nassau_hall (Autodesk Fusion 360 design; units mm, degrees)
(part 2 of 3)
sketch "Sketch47" plane through (0, 19.3945, 0) normal (0, 1, 0) x axis (-1, 0, 0)
  line L1 (-128, 3) -> (-132.5, 3)
  line L2 (-128, -6) -> (-128, 3)
  line L3 (-132.5, -6) -> (-128, -6)
  line L4 (-132.5, 3) -> (-132.5, -6)
  line L5 (-38, 3) -> (-42.5323, 3)
  line L6 (-38, -6.0191) -> (-38, 3)
  line L7 (-42.5323, -6.0191) -> (-38, -6.0191)
  line L8 (-42.5323, 3) -> (-42.5323, -6.0191)
  line L9 (-128, 26) -> (-132.5, 26)
  line L10 (-128, 17) -> (-128, 26)
  line L11 (-132.5, 17) -> (-128, 17)
  line L12 (-132.5, 26) -> (-132.5, 17)
  line L13 (-53, 3) -> (-57.5, 3)
  line L14 (-53, -6) -> (-53, 3)
  line L15 (-57.5, -6) -> (-53, -6)
  line L16 (-57.5, 3) -> (-57.5, -6)
  line L17 (-98, 3) -> (-102.5, 3)
  line L18 (-98, -6) -> (-98, 3)
  line L19 (-102.5, -6) -> (-98, -6)
  line L20 (-102.5, 3) -> (-102.5, -6)
  line L21 (-83, 26) -> (-87.5, 26)
  line L22 (-83, 17) -> (-83, 26)
  line L23 (-87.5, 17) -> (-83, 17)
  line L24 (-87.5, 26) -> (-87.5, 17)
  line L25 (-38, 45) -> (-42.5, 45)
  line L26 (-38, 38) -> (-38, 45)
  line L27 (-42.5, 38) -> (-38, 38)
  line L28 (-42.5, 45) -> (-42.5, 38)
  line L29 (-98, 45) -> (-102.5, 45)
  line L30 (-98, 38) -> (-98, 45)
  line L31 (-102.5, 38) -> (-98, 38)
  line L32 (-102.5, 45) -> (-102.5, 38)
  line L33 (-143, 45) -> (-147.5, 45)
  line L34 (-143, 38) -> (-143, 45)
  line L35 (-147.5, 38) -> (-143, 38)
  line L36 (-147.5, 45) -> (-147.5, 38)
  line L37 (-83, 45) -> (-87.5, 45)
  line L38 (-83, 38) -> (-83, 45)
  line L39 (-87.5, 38) -> (-83, 38)
  line L40 (-87.5, 45) -> (-87.5, 38)
  line L41 (-38, 26) -> (-42.5, 26)
  line L42 (-38, 17) -> (-38, 26)
  line L43 (-42.5, 17) -> (-38, 17)
  line L44 (-42.5, 26) -> (-42.5, 17)
  line L45 (-98, 26) -> (-102.5, 26)
  line L46 (-98, 17) -> (-98, 26)
  line L47 (-102.5, 17) -> (-98, 17)
  line L48 (-102.5, 26) -> (-102.5, 17)
  line L49 (-68, 26) -> (-72.5, 26)
  line L50 (-68, 17) -> (-68, 26)
  line L51 (-72.5, 17) -> (-68, 17)
  line L52 (-72.5, 26) -> (-72.5, 17)
  line L53 (-53, 45) -> (-57.5, 45)
  line L54 (-53, 38) -> (-53, 45)
  line L55 (-57.5, 38) -> (-53, 38)
  line L56 (-57.5, 45) -> (-57.5, 38)
  line L57 (-113, 45) -> (-117.5, 45)
  line L58 (-113, 38) -> (-113, 45)
  line L59 (-117.5, 38) -> (-113, 38)
  line L60 (-117.5, 45) -> (-117.5, 38)
  line L61 (-128, 45) -> (-132.5, 45)
  line L62 (-128, 38) -> (-128, 45)
  line L63 (-132.5, 38) -> (-128, 38)
  line L64 (-132.5, 45) -> (-132.5, 38)
  line L65 (-68, 45) -> (-72.5, 45)
  line L66 (-68, 38) -> (-68, 45)
  line L67 (-72.5, 38) -> (-68, 38)
  line L68 (-72.5, 45) -> (-72.5, 38)
  line L69 (-53, 26) -> (-57.5, 26)
  line L70 (-53, 17) -> (-53, 26)
  line L71 (-57.5, 17) -> (-53, 17)
  line L72 (-57.5, 26) -> (-57.5, 17)
  line L73 (-113, 26) -> (-117.5, 26)
  line L74 (-113, 16.9958) -> (-113, 26)
  line L75 (-117.5, 16.9958) -> (-113, 16.9958)
  line L76 (-117.5, 26) -> (-117.5, 16.9958)
  line L77 (-83, 3) -> (-87.5, 3)
  line L78 (-83, -6) -> (-83, 3)
  line L79 (-87.5, -6) -> (-83, -6)
  line L80 (-87.5, 3) -> (-87.5, -6)
  line L81 (-143, 3) -> (-147.5, 3)
  line L82 (-143, -6) -> (-143, 3)
  line L83 (-147.5, -6) -> (-143, -6)
  line L84 (-147.5, 3) -> (-147.5, -6)
  line L85 (-143, 26) -> (-147.5, 26)
  line L86 (-143, 17) -> (-143, 26)
  line L87 (-147.5, 17) -> (-143, 17)
  line L88 (-147.5, 26) -> (-147.5, 17)
  line L89 (-68, 3) -> (-72.5, 3)
  line L90 (-68, -6) -> (-68, 3)
  line L91 (-72.5, -6) -> (-68, -6)
  line L92 (-72.5, 3) -> (-72.5, -6)
  line L93 (-113, 3) -> (-117.5, 3)
  line L94 (-113, -6) -> (-113, 3)
  line L95 (-117.5, -6) -> (-113, -6)
  line L96 (-117.5, 3) -> (-117.5, -6)
  line L97 (-33.9524, -14.3624) -> (-160.4524, -14.3624)
  line L98 (-33.9524, 57.1376) -> (-33.9524, -14.3624)
  line L99 (-130.4524, 57.1376) -> (-33.9524, 57.1376)
  line L100 (-130.4524, 55.1376) -> (-130.4524, 57.1376)
  line L101 (-160.4524, 55.1376) -> (-130.4524, 55.1376)
  line L102 (-160.4524, -14.3624) -> (-160.4524, 55.1376)
  line L103 (-2, 3) -> (-6, 3)
  line L104 (-2, -6) -> (-2, 3)
  line L105 (-6, -6) -> (-2, -6)
  line L106 (-6, 3) -> (-6, -6)
  horizontal L103
  vertical L104
  horizontal L105
  vertical L106
sketch "Sketch48" plane through (0, -63.1055, 0) normal (0, -1, 0) x axis (1, 0, 0)
  line L1 (-41.0476, -14.3624) -> (-167.5476, -14.3624)
  line L2 (-41.0476, 57.1376) -> (-41.0476, -14.3624)
  line L3 (-137.5476, 57.1376) -> (-41.0476, 57.1376)
  line L4 (-137.5476, 55.1376) -> (-137.5476, 57.1376)
  line L5 (-167.5476, 55.1376) -> (-137.5476, 55.1376)
  line L6 (-167.5476, -14.3624) -> (-167.5476, 55.1376)
sketch "Sketch49" plane through (0, 19.3945, 0) normal (0, 1, 0) x axis (-1, 0, 0)
  line L1 (124.5, 38) -> (124.5, 45)
  line L2 (120, 38) -> (124.5, 38)
  line L3 (120, 45) -> (120, 38)
  line L4 (124.5, 45) -> (120, 45)
  line L5 (64.5, 38) -> (64.5, 45)
  line L6 (60, 38) -> (64.5, 38)
  line L7 (60, 45) -> (60, 38)
  line L8 (64.5, 45) -> (60, 45)
  line L9 (79.5, 38) -> (79.5, 45)
  line L10 (75, 38) -> (79.5, 38)
  line L11 (75, 45) -> (75, 38)
  line L12 (79.5, 45) -> (75, 45)
  line L13 (139.5, 38) -> (139.5, 45)
  line L14 (135, 38) -> (139.5, 38)
  line L15 (135, 45) -> (135, 38)
  line L16 (139.5, 45) -> (135, 45)
  line L17 (109.5, 38) -> (109.5, 45)
  line L18 (105, 38) -> (109.5, 38)
  line L19 (105, 45) -> (105, 38)
  line L20 (109.5, 45) -> (105, 45)
  line L21 (49.5, 38) -> (49.5, 45)
  line L22 (45, 38) -> (49.5, 38)
  line L23 (45, 45) -> (45, 38)
  line L24 (49.5, 45) -> (45, 45)
  line L25 (94.5, 38) -> (94.5, 45)
  line L26 (90, 38) -> (94.5, 38)
  line L27 (90, 45) -> (90, 38)
  line L28 (94.5, 45) -> (90, 45)
  line L29 (154.5, 38) -> (154.5, 45)
  line L30 (150, 38) -> (154.5, 38)
  line L31 (150, 45) -> (150, 38)
  line L32 (154.5, 45) -> (150, 45)
  line L33 (49.5133, -6) -> (49.5133, 3)
  line L34 (45, -6) -> (49.5133, -6)
  line L35 (45, 3) -> (45, -6)
  line L36 (49.5133, 3) -> (45, 3)
  line L37 (154.5, -6) -> (154.5, 3)
  line L38 (150, -6) -> (154.5, -6)
  line L39 (150, 3) -> (150, -6)
  line L40 (154.5, 3) -> (150, 3)
  line L41 (109.5, 17) -> (109.5, 26)
  line L42 (105, 17) -> (109.5, 17)
  line L43 (105, 26) -> (105, 17)
  line L44 (109.5, 26) -> (105, 26)
  line L45 (79.5, -6) -> (79.5, 3)
  line L46 (75, -6) -> (79.5, -6)
  line L47 (75, 3) -> (75, -6)
  line L48 (79.5, 3) -> (75, 3)
  line L49 (64.5, 17) -> (64.5, 26)
  line L50 (60, 17) -> (64.5, 17)
  line L51 (60, 26) -> (60, 17)
  line L52 (64.5, 26) -> (60, 26)
  line L53 (94.5, 17) -> (94.5, 26)
  line L54 (90, 17) -> (94.5, 17)
  line L55 (90, 26) -> (90, 17)
  line L56 (94.5, 26) -> (90, 26)
  line L57 (124.5, 17) -> (124.5, 26)
  line L58 (120, 17) -> (124.5, 17)
  line L59 (120, 26) -> (120, 17)
  line L60 (124.5, 26) -> (120, 26)
  line L61 (124.5, -6) -> (124.5, 3)
  line L62 (120, -6) -> (124.5, -6)
  line L63 (120, 3) -> (120, -6)
  line L64 (124.5, 3) -> (120, 3)
  line L65 (154.5, 17) -> (154.5, 26)
  line L66 (150, 17) -> (154.5, 17)
  line L67 (150, 26) -> (150, 17)
  line L68 (154.5, 26) -> (150, 26)
  line L69 (109.5, -6) -> (109.5, 3)
  line L70 (105, -6) -> (109.5, -6)
  line L71 (105, 3) -> (105, -6)
  line L72 (109.5, 3) -> (105, 3)
  line L73 (79.5, 17) -> (79.5, 26)
  line L74 (75, 17) -> (79.5, 17)
  line L75 (75, 26) -> (75, 17)
  line L76 (79.5, 26) -> (75, 26)
  line L77 (64.5, -6) -> (64.5, 3)
  line L78 (60, -6) -> (64.5, -6)
  line L79 (60, 3) -> (60, -6)
  line L80 (64.5, 3) -> (60, 3)
  line L81 (94.5, -6) -> (94.5, 3)
  line L82 (90, -6) -> (94.5, -6)
  line L83 (90, 3) -> (90, -6)
  line L84 (94.5, 3) -> (90, 3)
  line L85 (139.5, 17) -> (139.5, 26)
  line L86 (135, 17) -> (139.5, 17)
  line L87 (135, 26) -> (135, 17)
  line L88 (139.5, 26) -> (135, 26)
  line L89 (139.5, -6) -> (139.5, 3)
  line L90 (135, -6) -> (139.5, -6)
  line L91 (135, 3) -> (135, -6)
  line L92 (139.5, 3) -> (135, 3)
  line L93 (49.5073, 17) -> (49.5073, 26)
  line L94 (45, 17) -> (49.5073, 17)
  line L95 (45, 26) -> (45, 17)
  line L96 (49.5073, 26) -> (45, 26)
  line L97 (167.5476, -14.3624) -> (41.0476, -14.3624)
  line L98 (167.5476, 55.1376) -> (167.5476, -14.3624)
  line L99 (137.5476, 55.1376) -> (167.5476, 55.1376)
  line L100 (137.5476, 57.1376) -> (137.5476, 55.1376)
  line L101 (41.0476, 57.1376) -> (137.5476, 57.1376)
  line L102 (41.0476, -14.3624) -> (41.0476, 57.1376)
sketch "Sketch50" plane through (0, 19.3945, 0) normal (0, 1, 0) x axis (-1, 0, 0)
extrude "Extrude39" cut sketch "Sketch49" profile of L93 L94 L95 L96 against normal blind 100
extrude "Extrude40" cut sketch "Sketch47" profile of L5 L6 L7 L8 L13 L14 L15 L16 L17 L18 L19 L20 L77 L78 L79 L80 L89 L90 L91 L92 L93 L94 L95 L96 against normal blind 100
sketch "Sketch51" plane through (0, -61.1302, 0) normal (0, 1, 0) x axis (-1, 0, 0)
  line L1 (-33.9524, -14.3624) -> (-157.9638, -14.3624)
  line L2 (-33.9524, 55.6376) -> (-33.9524, -14.3624)
  line L3 (-157.9638, 55.6376) -> (-33.9524, 55.6376)
  line L4 (-157.9638, -14.3624) -> (-157.9638, 55.6376)
  line L5 (-38, -6.0191) -> (-38, 3)
  line L6 (-42.5323, -6.0191) -> (-38, -6.0191)
  line L7 (-42.5323, 3) -> (-42.5323, -6.0191)
  line L8 (-38, 3) -> (-42.5323, 3)
  line L9 (-98, -6) -> (-98, 3)
  line L10 (-102.5, -6) -> (-98, -6)
  line L11 (-102.5, 3) -> (-102.5, -6)
  line L12 (-98, 3) -> (-102.5, 3)
  line L13 (-83, -6) -> (-83, 3)
  line L14 (-87.5, -6) -> (-83, -6)
  line L15 (-87.5, 3) -> (-87.5, -6)
  line L16 (-83, 3) -> (-87.5, 3)
  line L17 (-53, -6) -> (-53, 3)
  line L18 (-57.5, -6) -> (-53, -6)
  line L19 (-57.5, 3) -> (-57.5, -6)
  line L20 (-53, 3) -> (-57.5, 3)
  line L21 (-113, -6) -> (-113, 3)
  line L22 (-117.5, -6) -> (-113, -6)
  line L23 (-117.5, 3) -> (-117.5, -6)
  line L24 (-113, 3) -> (-117.5, 3)
  line L25 (-68, -6) -> (-68, 3)
  line L26 (-72.5, -6) -> (-68, -6)
  line L27 (-72.5, 3) -> (-72.5, -6)
  line L28 (-68, 3) -> (-72.5, 3)
sketch "Sketch52" plane through (0, -61, 0) normal (0, 1, 0) x axis (-1, 0, 0)
  line L1 (45, 17) -> (49.5073, 17)
  line L2 (45, 26) -> (45, 17)
  line L3 (49.5073, 26) -> (45, 26)
  line L4 (49.5073, 17) -> (49.5073, 26)
  line L5 (166, -14.3624) -> (41.0476, -14.3624)
  line L6 (166, 55.6376) -> (166, -14.3624)
  line L7 (41.0476, 55.6376) -> (166, 55.6376)
  line L8 (41.0476, -14.3624) -> (41.0476, 55.6376)
  line L9 (64.5607, 26) -> (60, 26)
  line L10 (64.5607, 16.951) -> (64.5607, 26)
  line L11 (60, 16.951) -> (64.5607, 16.951)
  line L12 (60, 26) -> (60, 16.951)
  horizontal L9
  vertical L10
  horizontal L11
  vertical L12
extrude "Extrude41" cut sketch "Sketch52" profile of L9 L10 L11 L12 against normal blind 100
sketch "Sketch53" plane through (0, 19.3945, 0) normal (0, 1, 0) x axis (-1, 0, 0)
  line L1 (124.5, 38) -> (124.5, 45)
  line L2 (120, 38) -> (124.5, 38)
  line L3 (120, 45) -> (120, 38)
  line L4 (124.5, 45) -> (120, 45)
  line L5 (64.5, 38) -> (64.5, 45)
  line L6 (60, 38) -> (64.5, 38)
  line L7 (60, 45) -> (60, 38)
  line L8 (64.5, 45) -> (60, 45)
  line L9 (79.5, 38) -> (79.5, 45)
  line L10 (75, 38) -> (79.5, 38)
  line L11 (75, 45) -> (75, 38)
  line L12 (79.5, 45) -> (75, 45)
  line L13 (139.5, 38) -> (139.5, 45)
  line L14 (135, 38) -> (139.5, 38)
  line L15 (135, 45) -> (135, 38)
  line L16 (139.5, 45) -> (135, 45)
  line L17 (109.5, 38) -> (109.5, 45)
  line L18 (105, 38) -> (109.5, 38)
  line L19 (105, 45) -> (105, 38)
  line L20 (109.5, 45) -> (105, 45)
  line L21 (49.5, 38) -> (49.5, 45)
  line L22 (45, 38) -> (49.5, 38)
  line L23 (45, 45) -> (45, 38)
  line L24 (49.5, 45) -> (45, 45)
  line L25 (94.5, 38) -> (94.5, 45)
  line L26 (90, 38) -> (94.5, 38)
  line L27 (90, 45) -> (90, 38)
  line L28 (94.5, 45) -> (90, 45)
  line L29 (154.5, 38) -> (154.5, 45)
  line L30 (150, 38) -> (154.5, 38)
  line L31 (150, 45) -> (150, 38)
  line L32 (154.5, 45) -> (150, 45)
  line L33 (49.5133, -6) -> (49.5133, 3)
  line L34 (45, -6) -> (49.5133, -6)
  line L35 (45, 3) -> (45, -6)
  line L36 (49.5133, 3) -> (45, 3)
  line L37 (154.5, -6) -> (154.5, 3)
  line L38 (150, -6) -> (154.5, -6)
  line L39 (150, 3) -> (150, -6)
  line L40 (154.5, 3) -> (150, 3)
  line L41 (109.5, 17) -> (109.5, 26)
  line L42 (105, 17) -> (109.5, 17)
  line L43 (105, 26) -> (105, 17)
  line L44 (109.5, 26) -> (105, 26)
  line L45 (79.5, -6) -> (79.5, 3)
  line L46 (75, -6) -> (79.5, -6)
  line L47 (75, 3) -> (75, -6)
  line L48 (79.5, 3) -> (75, 3)
  line L49 (64.5, 17) -> (64.5, 26)
  line L50 (60, 17) -> (64.5, 17)
  line L51 (60, 26) -> (60, 17)
  line L52 (64.5, 26) -> (60, 26)
  line L53 (94.5, 17) -> (94.5, 26)
  line L54 (90, 17) -> (94.5, 17)
  line L55 (90, 26) -> (90, 17)
  line L56 (94.5, 26) -> (90, 26)
  line L57 (124.5, 17) -> (124.5, 26)
  line L58 (120, 17) -> (124.5, 17)
  line L59 (120, 26) -> (120, 17)
  line L60 (124.5, 26) -> (120, 26)
  line L61 (124.5, -6) -> (124.5, 3)
  line L62 (120, -6) -> (124.5, -6)
  line L63 (120, 3) -> (120, -6)
  line L64 (124.5, 3) -> (120, 3)
  line L65 (154.5, 17) -> (154.5, 26)
  line L66 (150, 17) -> (154.5, 17)
  line L67 (150, 26) -> (150, 17)
  line L68 (154.5, 26) -> (150, 26)
  line L69 (109.5, -6) -> (109.5, 3)
  line L70 (105, -6) -> (109.5, -6)
  line L71 (105, 3) -> (105, -6)
  line L72 (109.5, 3) -> (105, 3)
  line L73 (79.5, 17) -> (79.5, 26)
  line L74 (75, 17) -> (79.5, 17)
  line L75 (75, 26) -> (75, 17)
  line L76 (79.5, 26) -> (75, 26)
  line L77 (64.5, -6) -> (64.5, 3)
  line L78 (60, -6) -> (64.5, -6)
  line L79 (60, 3) -> (60, -6)
  line L80 (64.5, 3) -> (60, 3)
  line L81 (94.5, -6) -> (94.5, 3)
  line L82 (90, -6) -> (94.5, -6)
  line L83 (90, 3) -> (90, -6)
  line L84 (94.5, 3) -> (90, 3)
  line L85 (139.5, 17) -> (139.5, 26)
  line L86 (135, 17) -> (139.5, 17)
  line L87 (135, 26) -> (135, 17)
  line L88 (139.5, 26) -> (135, 26)
  line L89 (139.5, -6) -> (139.5, 3)
  line L90 (135, -6) -> (139.5, -6)
  line L91 (135, 3) -> (135, -6)
  line L92 (139.5, 3) -> (135, 3)
  line L93 (49.5073, 17) -> (49.5073, 26)
  line L94 (45, 17) -> (49.5073, 17)
  line L95 (45, 26) -> (45, 17)
  line L96 (49.5073, 26) -> (45, 26)
  line L97 (167.5476, -14.3624) -> (41.0476, -14.3624)
  line L98 (167.5476, 55.1376) -> (167.5476, -14.3624)
  line L99 (137.5476, 55.1376) -> (167.5476, 55.1376)
  line L100 (137.5476, 57.1376) -> (137.5476, 55.1376)
  line L101 (41.0476, 57.1376) -> (137.5476, 57.1376)
  line L102 (41.0476, -14.3624) -> (41.0476, 57.1376)
extrude "Extrude39" new body sketch "Sketch53" profile of L21 L22 L23 L24 along normal blind 100
extrude "Extrude40" cut of existing geometry blind -200
sketch "Sketch54" plane through (0, -61, 0) normal (0, 1, 0) x axis (-1, 0, 0)
  line L1 (45, 38) -> (49.5, 38)
  line L2 (45, 45) -> (45, 38)
  line L3 (49.5, 45) -> (45, 45)
  line L4 (49.5, 38) -> (49.5, 45)
  line L5 (64.5607, 16.951) -> (64.5607, 26)
  line L6 (60, 16.951) -> (64.5607, 16.951)
  line L7 (60, 26) -> (60, 16.951)
  line L8 (64.5607, 26) -> (60, 26)
  line L9 (45, 17) -> (49.5073, 17)
  line L10 (45, 26) -> (45, 17)
  line L11 (49.5073, 26) -> (45, 26)
  line L12 (49.5073, 17) -> (49.5073, 26)
  line L13 (166, -14.3624) -> (41.0476, -14.3624)
  line L14 (166, 55.6376) -> (166, -14.3624)
  line L15 (41.0476, 55.6376) -> (166, 55.6376)
  line L16 (41.0476, -14.3624) -> (41.0476, 55.6376)
  line L17 (49.4925, 3) -> (45, 3)
  line L18 (49.4925, -5.9059) -> (49.4925, 3)
  line L19 (45, -5.9059) -> (49.4925, -5.9059)
  line L20 (45, 3) -> (45, -5.9059)
  line L21 (64.5, 3) -> (60, 3)
  line L22 (64.5, -6) -> (64.5, 3)
  line L23 (60, -6) -> (64.5, -6)
  line L24 (60, 3) -> (60, -6)
  line L25 (64.5, 45) -> (60, 45)
  line L26 (64.5, 37.9022) -> (64.5, 45)
  line L27 (60, 37.9022) -> (64.5, 37.9022)
  line L28 (60, 45) -> (60, 37.9022)
  horizontal L17
  vertical L18
  horizontal L19
  vertical L20
  horizontal L21
  vertical L22
  horizontal L23
  vertical L24
  horizontal L25
  vertical L26
  horizontal L27
  vertical L28
extrude "Extrude43" cut sketch "Sketch54" profile of L17 L18 L19 L20 L21 L22 L23 L24 L25 L26 L27 L28 against normal blind 100
sketch "Sketch55" plane through (0, 19.3945, 0) normal (0, 1, 0) x axis (-1, 0, 0)
  line L1 (124.5, 38) -> (124.5, 45)
  line L2 (120, 38) -> (124.5, 38)
  line L3 (120, 45) -> (120, 38)
  line L4 (124.5, 45) -> (120, 45)
  line L5 (64.5, 38) -> (64.5, 45)
  line L6 (60, 38) -> (64.5, 38)
  line L7 (60, 45) -> (60, 38)
  line L8 (64.5, 45) -> (60, 45)
  line L9 (79.5, 38) -> (79.5, 45)
  line L10 (75, 38) -> (79.5, 38)
  line L11 (75, 45) -> (75, 38)
  line L12 (79.5, 45) -> (75, 45)
  line L13 (139.5, 38) -> (139.5, 45)
  line L14 (135, 38) -> (139.5, 38)
  line L15 (135, 45) -> (135, 38)
  line L16 (139.5, 45) -> (135, 45)
  line L17 (109.5, 38) -> (109.5, 45)
  line L18 (105, 38) -> (109.5, 38)
  line L19 (105, 45) -> (105, 38)
  line L20 (109.5, 45) -> (105, 45)
  line L21 (49.5, 38) -> (49.5, 45)
  line L22 (45, 38) -> (49.5, 38)
  line L23 (45, 45) -> (45, 38)
  line L24 (49.5, 45) -> (45, 45)
  line L25 (94.5, 38) -> (94.5, 45)
  line L26 (90, 38) -> (94.5, 38)
  line L27 (90, 45) -> (90, 38)
  line L28 (94.5, 45) -> (90, 45)
  line L29 (154.5, 38) -> (154.5, 45)
  line L30 (150, 38) -> (154.5, 38)
  line L31 (150, 45) -> (150, 38)
  line L32 (154.5, 45) -> (150, 45)
  line L33 (49.5133, -6) -> (49.5133, 3)
  line L34 (45, -6) -> (49.5133, -6)
  line L35 (45, 3) -> (45, -6)
  line L36 (49.5133, 3) -> (45, 3)
  line L37 (154.5, -6) -> (154.5, 3)
  line L38 (150, -6) -> (154.5, -6)
  line L39 (150, 3) -> (150, -6)
  line L40 (154.5, 3) -> (150, 3)
  line L41 (109.5, 17) -> (109.5, 26)
  line L42 (105, 17) -> (109.5, 17)
  line L43 (105, 26) -> (105, 17)
  line L44 (109.5, 26) -> (105, 26)
  line L45 (79.5, -6) -> (79.5, 3)
  line L46 (75, -6) -> (79.5, -6)
  line L47 (75, 3) -> (75, -6)
  line L48 (79.5, 3) -> (75, 3)
  line L49 (64.5, 17) -> (64.5, 26)
  line L50 (60, 17) -> (64.5, 17)
  line L51 (60, 26) -> (60, 17)
  line L52 (64.5, 26) -> (60, 26)
  line L53 (94.5, 17) -> (94.5, 26)
  line L54 (90, 17) -> (94.5, 17)
  line L55 (90, 26) -> (90, 17)
  line L56 (94.5, 26) -> (90, 26)
  line L57 (124.5, 17) -> (124.5, 26)
  line L58 (120, 17) -> (124.5, 17)
  line L59 (120, 26) -> (120, 17)
  line L60 (124.5, 26) -> (120, 26)
  line L61 (124.5, -6) -> (124.5, 3)
  line L62 (120, -6) -> (124.5, -6)
  line L63 (120, 3) -> (120, -6)
  line L64 (124.5, 3) -> (120, 3)
  line L65 (154.5, 17) -> (154.5, 26)
  line L66 (150, 17) -> (154.5, 17)
  line L67 (150, 26) -> (150, 17)
  line L68 (154.5, 26) -> (150, 26)
  line L69 (109.5, -6) -> (109.5, 3)
  line L70 (105, -6) -> (109.5, -6)
  line L71 (105, 3) -> (105, -6)
  line L72 (109.5, 3) -> (105, 3)
  line L73 (79.5, 17) -> (79.5, 26)
  line L74 (75, 17) -> (79.5, 17)
  line L75 (75, 26) -> (75, 17)
  line L76 (79.5, 26) -> (75, 26)
  line L77 (64.5, -6) -> (64.5, 3)
  line L78 (60, -6) -> (64.5, -6)
  line L79 (60, 3) -> (60, -6)
  line L80 (64.5, 3) -> (60, 3)
  line L81 (94.5, -6) -> (94.5, 3)
  line L82 (90, -6) -> (94.5, -6)
  line L83 (90, 3) -> (90, -6)
  line L84 (94.5, 3) -> (90, 3)
  line L85 (139.5, 17) -> (139.5, 26)
  line L86 (135, 17) -> (139.5, 17)
  line L87 (135, 26) -> (135, 17)
  line L88 (139.5, 26) -> (135, 26)
  line L89 (139.5, -6) -> (139.5, 3)
  line L90 (135, -6) -> (139.5, -6)
  line L91 (135, 3) -> (135, -6)
  line L92 (139.5, 3) -> (135, 3)
  line L93 (49.5073, 17) -> (49.5073, 26)
  line L94 (45, 17) -> (49.5073, 17)
  line L95 (45, 26) -> (45, 17)
  line L96 (49.5073, 26) -> (45, 26)
  line L97 (167.5476, -14.3624) -> (41.0476, -14.3624)
  line L98 (167.5476, 55.1376) -> (167.5476, -14.3624)
  line L99 (137.5476, 55.1376) -> (167.5476, 55.1376)
  line L100 (137.5476, 57.1376) -> (137.5476, 55.1376)
  line L101 (41.0476, 57.1376) -> (137.5476, 57.1376)
  line L102 (41.0476, -14.3624) -> (41.0476, 57.1376)
  line L103 (79.5, 45) -> (75, 45)
  line L104 (79.5, 38) -> (79.5, 45)
  line L105 (75, 38) -> (79.5, 38)
  line L106 (75, 45) -> (75, 38)
  line L107 (79.5, 26) -> (75, 26)
  line L108 (79.5, 17) -> (79.5, 26)
  line L109 (75, 17) -> (79.5, 17)
  line L110 (75, 26) -> (75, 17)
  line L111 (79.5, 2.7917) -> (75, 2.7917)
  line L112 (79.5, -6) -> (79.5, 2.7917)
  line L113 (75, -6) -> (79.5, -6)
  line L114 (75, 2.7917) -> (75, -6)
  point P11 (79.5, 38)
  point P106 (79.5, 38)
  point P13 (75, 45)
  point P104 (75, 45)
  point P75 (79.5, 17)
  point P110 (79.5, 17)
  point P77 (75, 26)
  point P108 (75, 26)
  point P47 (79.5, -6)
  point P114 (79.5, -6)
  point P112 (75, 2.7917)
  horizontal L103
  vertical L104
  horizontal L105
  vertical L106
  coincident P11 P106
  coincident P13 P104
  horizontal L107
  vertical L108
  horizontal L109
  vertical L110
  coincident P75 P110
  coincident P77 P108
  horizontal L111
  vertical L112
  horizontal L113
  vertical L114
  coincident P47 P114
  coincident L47 P112
extrude "Extrude44" cut sketch "Sketch55" profile of L9 L10 L11 L12 L45 L46 L47 L73 L74 L75 L76 L103 L104 L105 L106 L107 L108 L109 L110 L111 L112 L113 L114 against normal blind 100
sketch "Sketch56" plane through (0, 19.3945, 0) normal (0, 1, 0) x axis (-1, 0, 0)
  line L1 (124.5, 38) -> (124.5, 45)
  line L2 (120, 38) -> (124.5, 38)
  line L3 (120, 45) -> (120, 38)
  line L4 (124.5, 45) -> (120, 45)
  line L5 (64.5, 38) -> (64.5, 45)
  line L6 (60, 38) -> (64.5, 38)
  line L7 (60, 45) -> (60, 38)
  line L8 (64.5, 45) -> (60, 45)
  line L9 (79.5, 38) -> (79.5, 45)
  line L10 (75, 38) -> (79.5, 38)
  line L11 (75, 45) -> (75, 38)
  line L12 (79.5, 45) -> (75, 45)
  line L13 (139.5, 38) -> (139.5, 45)
  line L14 (135, 38) -> (139.5, 38)
  line L15 (135, 45) -> (135, 38)
  line L16 (139.5, 45) -> (135, 45)
  line L17 (109.5, 38) -> (109.5, 45)
  line L18 (105, 38) -> (109.5, 38)
  line L19 (105, 45) -> (105, 38)
  line L20 (109.5, 45) -> (105, 45)
  line L21 (49.5, 38) -> (49.5, 45)
  line L22 (45, 38) -> (49.5, 38)
  line L23 (45, 45) -> (45, 38)
  line L24 (49.5, 45) -> (45, 45)
  line L25 (94.5, 38) -> (94.5, 45)
  line L26 (90, 38) -> (94.5, 38)
  line L27 (90, 45) -> (90, 38)
  line L28 (94.5, 45) -> (90, 45)
  line L29 (154.5, 38) -> (154.5, 45)
  line L30 (150, 38) -> (154.5, 38)
  line L31 (150, 45) -> (150, 38)
  line L32 (154.5, 45) -> (150, 45)
  line L33 (49.5133, -6) -> (49.5133, 3)
  line L34 (45, -6) -> (49.5133, -6)
  line L35 (45, 3) -> (45, -6)
  line L36 (49.5133, 3) -> (45, 3)
  line L37 (154.5, -6) -> (154.5, 3)
  line L38 (150, -6) -> (154.5, -6)
  line L39 (150, 3) -> (150, -6)
  line L40 (154.5, 3) -> (150, 3)
  line L41 (109.5, 17) -> (109.5, 26)
  line L42 (105, 17) -> (109.5, 17)
  line L43 (105, 26) -> (105, 17)
  line L44 (109.5, 26) -> (105, 26)
  line L45 (79.5, -6) -> (79.5, 3)
  line L46 (75, -6) -> (79.5, -6)
  line L47 (75, 3) -> (75, -6)
  line L48 (79.5, 3) -> (75, 3)
  line L49 (64.5, 17) -> (64.5, 26)
  line L50 (60, 17) -> (64.5, 17)
  line L51 (60, 26) -> (60, 17)
  line L52 (64.5, 26) -> (60, 26)
  line L53 (94.5, 17) -> (94.5, 26)
  line L54 (90, 17) -> (94.5, 17)
  line L55 (90, 26) -> (90, 17)
  line L56 (94.5, 26) -> (90, 26)
  line L57 (124.5, 17) -> (124.5, 26)
  line L58 (120, 17) -> (124.5, 17)
  line L59 (120, 26) -> (120, 17)
  line L60 (124.5, 26) -> (120, 26)
  line L61 (124.5, -6) -> (124.5, 3)
  line L62 (120, -6) -> (124.5, -6)
  line L63 (120, 3) -> (120, -6)
  line L64 (124.5, 3) -> (120, 3)
  line L65 (154.5, 17) -> (154.5, 26)
  line L66 (150, 17) -> (154.5, 17)
  line L67 (150, 26) -> (150, 17)
  line L68 (154.5, 26) -> (150, 26)
  line L69 (109.5, -6) -> (109.5, 3)
  line L70 (105, -6) -> (109.5, -6)
  line L71 (105, 3) -> (105, -6)
  line L72 (109.5, 3) -> (105, 3)
  line L73 (79.5, 17) -> (79.5, 26)
  line L74 (75, 17) -> (79.5, 17)
  line L75 (75, 26) -> (75, 17)
  line L76 (79.5, 26) -> (75, 26)
  line L77 (64.5, -6) -> (64.5, 3)
  line L78 (60, -6) -> (64.5, -6)
  line L79 (60, 3) -> (60, -6)
  line L80 (64.5, 3) -> (60, 3)
  line L81 (94.5, -6) -> (94.5, 3)
  line L82 (90, -6) -> (94.5, -6)
  line L83 (90, 3) -> (90, -6)
  line L84 (94.5, 3) -> (90, 3)
  line L85 (139.5, 17) -> (139.5, 26)
  line L86 (135, 17) -> (139.5, 17)
  line L87 (135, 26) -> (135, 17)
  line L88 (139.5, 26) -> (135, 26)
  line L89 (139.5, -6) -> (139.5, 3)
  line L90 (135, -6) -> (139.5, -6)
  line L91 (135, 3) -> (135, -6)
  line L92 (139.5, 3) -> (135, 3)
  line L93 (49.5073, 17) -> (49.5073, 26)
  line L94 (45, 17) -> (49.5073, 17)
  line L95 (45, 26) -> (45, 17)
  line L96 (49.5073, 26) -> (45, 26)
  line L97 (167.5476, -14.3624) -> (41.0476, -14.3624)
  line L98 (167.5476, 55.1376) -> (167.5476, -14.3624)
  line L99 (137.5476, 55.1376) -> (167.5476, 55.1376)
  line L100 (137.5476, 57.1376) -> (137.5476, 55.1376)
  line L101 (41.0476, 57.1376) -> (137.5476, 57.1376)
  line L102 (41.0476, -14.3624) -> (41.0476, 57.1376)
extrude "Extrude45" cut sketch "Sketch56" profile of L1 L2 L3 L4 L13 L14 L15 L16 L17 L18 L19 L20 L25 L26 L27 L28 L29 L30 L31 L32 L37 L38 L39 L40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 against normal blind 100
sketch "Sketch57" plane through (0, 19.3945, 0) normal (0, 1, 0) x axis (-1, 0, 0)
  line L1 (-128, 3) -> (-132.5, 3)
  line L2 (-128, -6) -> (-128, 3)
  line L3 (-132.5, -6) -> (-128, -6)
  line L4 (-132.5, 3) -> (-132.5, -6)
  line L5 (-38, 3) -> (-42.5323, 3)
  line L6 (-38, -6.0191) -> (-38, 3)
  line L7 (-42.5323, -6.0191) -> (-38, -6.0191)
  line L8 (-42.5323, 3) -> (-42.5323, -6.0191)
  line L9 (-128, 26) -> (-132.5, 26)
  line L10 (-128, 17) -> (-128, 26)
  line L11 (-132.5, 17) -> (-128, 17)
  line L12 (-132.5, 26) -> (-132.5, 17)
  line L13 (-53, 3) -> (-57.5, 3)
  line L14 (-53, -6) -> (-53, 3)
  line L15 (-57.5, -6) -> (-53, -6)
  line L16 (-57.5, 3) -> (-57.5, -6)
  line L17 (-98, 3) -> (-102.5, 3)
  line L18 (-98, -6) -> (-98, 3)
  line L19 (-102.5, -6) -> (-98, -6)
  line L20 (-102.5, 3) -> (-102.5, -6)
  line L21 (-83, 26) -> (-87.5, 26)
  line L22 (-83, 17) -> (-83, 26)
  line L23 (-87.5, 17) -> (-83, 17)
  line L24 (-87.5, 26) -> (-87.5, 17)
  line L25 (-38, 45) -> (-42.5, 45)
  line L26 (-38, 38) -> (-38, 45)
  line L27 (-42.5, 38) -> (-38, 38)
  line L28 (-42.5, 45) -> (-42.5, 38)
  line L29 (-98, 45) -> (-102.5, 45)
  line L30 (-98, 38) -> (-98, 45)
  line L31 (-102.5, 38) -> (-98, 38)
  line L32 (-102.5, 45) -> (-102.5, 38)
  line L33 (-143, 45) -> (-147.5, 45)
  line L34 (-143, 38) -> (-143, 45)
  line L35 (-147.5, 38) -> (-143, 38)
  line L36 (-147.5, 45) -> (-147.5, 38)
  line L37 (-83, 45) -> (-87.5, 45)
  line L38 (-83, 38) -> (-83, 45)
  line L39 (-87.5, 38) -> (-83, 38)
  line L40 (-87.5, 45) -> (-87.5, 38)
  line L41 (-38, 26) -> (-42.5, 26)
  line L42 (-38, 17) -> (-38, 26)
  line L43 (-42.5, 17) -> (-38, 17)
  line L44 (-42.5, 26) -> (-42.5, 17)
  line L45 (-98, 26) -> (-102.5, 26)
  line L46 (-98, 17) -> (-98, 26)
  line L47 (-102.5, 17) -> (-98, 17)
  line L48 (-102.5, 26) -> (-102.5, 17)
  line L49 (-68, 26) -> (-72.5, 26)
  line L50 (-68, 17) -> (-68, 26)
  line L51 (-72.5, 17) -> (-68, 17)
  line L52 (-72.5, 26) -> (-72.5, 17)
  line L53 (-53, 45) -> (-57.5, 45)
  line L54 (-53, 38) -> (-53, 45)
  line L55 (-57.5, 38) -> (-53, 38)
  line L56 (-57.5, 45) -> (-57.5, 38)
  line L57 (-113, 45) -> (-117.5, 45)
  line L58 (-113, 38) -> (-113, 45)
  line L59 (-117.5, 38) -> (-113, 38)
  line L60 (-117.5, 45) -> (-117.5, 38)
  line L61 (-128, 45) -> (-132.5, 45)
  line L62 (-128, 38) -> (-128, 45)
  line L63 (-132.5, 38) -> (-128, 38)
  line L64 (-132.5, 45) -> (-132.5, 38)
  line L65 (-68, 45) -> (-72.5, 45)
  line L66 (-68, 38) -> (-68, 45)
  line L67 (-72.5, 38) -> (-68, 38)
  line L68 (-72.5, 45) -> (-72.5, 38)
  line L69 (-53, 26) -> (-57.5, 26)
  line L70 (-53, 17) -> (-53, 26)
  line L71 (-57.5, 17) -> (-53, 17)
  line L72 (-57.5, 26) -> (-57.5, 17)
  line L73 (-113, 26) -> (-117.5, 26)
  line L74 (-113, 16.9958) -> (-113, 26)
  line L75 (-117.5, 16.9958) -> (-113, 16.9958)
  line L76 (-117.5, 26) -> (-117.5, 16.9958)
  line L77 (-83, 3) -> (-87.5, 3)
  line L78 (-83, -6) -> (-83, 3)
  line L79 (-87.5, -6) -> (-83, -6)
  line L80 (-87.5, 3) -> (-87.5, -6)
  line L81 (-143, 3) -> (-147.5, 3)
  line L82 (-143, -6) -> (-143, 3)
  line L83 (-147.5, -6) -> (-143, -6)
  line L84 (-147.5, 3) -> (-147.5, -6)
  line L85 (-143, 26) -> (-147.5, 26)
  line L86 (-143, 17) -> (-143, 26)
  line L87 (-147.5, 17) -> (-143, 17)
  line L88 (-147.5, 26) -> (-147.5, 17)
  line L89 (-68, 3) -> (-72.5, 3)
  line L90 (-68, -6) -> (-68, 3)
  line L91 (-72.5, -6) -> (-68, -6)
  line L92 (-72.5, 3) -> (-72.5, -6)
  line L93 (-113, 3) -> (-117.5, 3)
  line L94 (-113, -6) -> (-113, 3)
  line L95 (-117.5, -6) -> (-113, -6)
  line L96 (-117.5, 3) -> (-117.5, -6)
  line L97 (-33.9524, -14.3624) -> (-160.4524, -14.3624)
  line L98 (-33.9524, 57.1376) -> (-33.9524, -14.3624)
  line L99 (-130.4524, 57.1376) -> (-33.9524, 57.1376)
  line L100 (-130.4524, 55.1376) -> (-130.4524, 57.1376)
  line L101 (-160.4524, 55.1376) -> (-130.4524, 55.1376)
  line L102 (-160.4524, -14.3624) -> (-160.4524, 55.1376)
extrude "Extrude46" cut sketch "Sketch57" profile of L1 L2 L3 L4 L5 L6 L7 L8 L9 L10 L11 L12 L13 L14 L15 L16 L17 L18 L19 L20 L21 L22 L23 L24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 against normal blind 100
sketch "Sketch58" plane through (0, 57.3945, 0) normal (0, 1, 0) x axis (-1, 0, 0)
  line L1 (-33.9524, -14.3624) -> (-33.9524, -5.9924)
  line L2 (41.0476, -14.3624) -> (-33.9524, -14.3624)
  line L3 (41.0476, -5.9924) -> (41.0476, -14.3624)
  line L4 (41.0199, -5.9924) -> (41.0476, -5.9924)
  line L5 (41.0199, 3.0076) -> (41.0199, -5.9924)
  line L6 (41.0476, 3.0076) -> (41.0199, 3.0076)
  line L7 (41.0476, 16.8876) -> (41.0476, 3.0076)
  line L8 (41.0199, 16.8876) -> (41.0476, 16.8876)
  line L9 (41.0199, 25.8876) -> (41.0199, 16.8876)
  line L10 (41.0476, 25.8876) -> (41.0199, 25.8876)
  line L11 (41.0476, 37.9076) -> (41.0476, 25.8876)
  line L12 (41.0199, 37.9076) -> (41.0476, 37.9076)
  line L13 (41.0199, 44.9076) -> (41.0199, 37.9076)
  line L14 (41.0476, 44.9076) -> (41.0199, 44.9076)
  line L15 (41.0476, 55.1376) -> (41.0476, 44.9076)
  line L16 (-33.9524, 55.1376) -> (41.0476, 55.1376)
  line L17 (-33.9524, 44.9076) -> (-33.9524, 55.1376)
  line L18 (-33.9246, 44.9076) -> (-33.9524, 44.9076)
  line L19 (-33.9246, 37.9076) -> (-33.9246, 44.9076)
  line L20 (-33.9524, 37.9076) -> (-33.9246, 37.9076)
  line L21 (-33.9524, 25.8876) -> (-33.9524, 37.9076)
  line L22 (-33.9246, 25.8876) -> (-33.9524, 25.8876)
  line L23 (-33.9246, 16.8876) -> (-33.9246, 25.8876)
  line L24 (-33.9524, 16.8876) -> (-33.9246, 16.8876)
  line L25 (-33.9524, 3.0076) -> (-33.9524, 16.8876)
  line L26 (-33.9246, 3.0076) -> (-33.9524, 3.0076)
  line L27 (-33.9246, -5.9924) -> (-33.9246, 3.0076)
  line L28 (-33.9524, -5.9924) -> (-33.9246, -5.9924)
  line L29 (28.131, -5.9924) -> (28.131, 3.0076)
  line L30 (23.631, -5.9924) -> (28.131, -5.9924)
  line L31 (23.631, 3.0076) -> (23.631, -5.9924)
  line L32 (28.131, 3.0076) -> (23.631, 3.0076)
  line L33 (13.2421, -5.9924) -> (13.2421, 3.0076)
  line L34 (8.7421, -5.9924) -> (13.2421, -5.9924)
  line L35 (8.7421, 3.0076) -> (8.7421, -5.9924)
  line L36 (13.2421, 3.0076) -> (8.7421, 3.0076)
  line L37 (28.131, 16.8876) -> (28.131, 25.8876)
  line L38 (23.631, 16.8876) -> (28.131, 16.8876)
  line L39 (23.631, 25.8876) -> (23.631, 16.8876)
  line L40 (28.131, 25.8876) -> (23.631, 25.8876)
  line L41 (28.131, 37.9076) -> (28.131, 44.9076)
  line L42 (23.631, 37.9076) -> (28.131, 37.9076)
  line L43 (23.631, 44.9076) -> (23.631, 37.9076)
  line L44 (28.131, 44.9076) -> (23.631, 44.9076)
  line L45 (13.2421, 16.8876) -> (13.2421, 25.8876)
  line L46 (8.7421, 16.8876) -> (13.2421, 16.8876)
  line L47 (8.7421, 25.8876) -> (8.7421, 16.8876)
  line L48 (13.2421, 25.8876) -> (8.7421, 25.8876)
  line L49 (13.2421, 37.9076) -> (13.2421, 44.9076)
  line L50 (8.7421, 37.9076) -> (13.2421, 37.9076)
  line L51 (8.7421, 44.9076) -> (8.7421, 37.9076)
  line L52 (13.2421, 44.9076) -> (8.7421, 44.9076)
  line L53 (-1.6468, -5.9924) -> (-1.6468, 3.0076)
  line L54 (-6.1468, -5.9924) -> (-1.6468, -5.9924)
  line L55 (-6.1468, 3.0076) -> (-6.1468, -5.9924)
  line L56 (-1.6468, 3.0076) -> (-6.1468, 3.0076)
  line L57 (-16.5357, -5.9924) -> (-16.5357, 3.0076)
  line L58 (-21.0357, -5.9924) -> (-16.5357, -5.9924)
  line L59 (-21.0357, 3.0076) -> (-21.0357, -5.9924)
  line L60 (-16.5357, 3.0076) -> (-21.0357, 3.0076)
  line L61 (-1.6468, 16.8876) -> (-1.6468, 25.8876)
  line L62 (-6.1468, 16.8876) -> (-1.6468, 16.8876)
  line L63 (-6.1468, 25.8876) -> (-6.1468, 16.8876)
  line L64 (-1.6468, 25.8876) -> (-6.1468, 25.8876)
  line L65 (-1.6468, 37.9076) -> (-1.6468, 44.9076)
  line L66 (-6.1468, 37.9076) -> (-1.6468, 37.9076)
  line L67 (-6.1468, 44.9076) -> (-6.1468, 37.9076)
  line L68 (-1.6468, 44.9076) -> (-6.1468, 44.9076)
  line L69 (-16.5357, 16.8876) -> (-16.5357, 25.8876)
  line L70 (-21.0357, 16.8876) -> (-16.5357, 16.8876)
  line L71 (-21.0357, 25.8876) -> (-21.0357, 16.8876)
  line L72 (-16.5357, 25.8876) -> (-21.0357, 25.8876)
  line L73 (-16.5357, 37.9076) -> (-16.5357, 44.9076)
  line L74 (-21.0357, 37.9076) -> (-16.5357, 37.9076)
  line L75 (-21.0357, 44.9076) -> (-21.0357, 37.9076)
  line L76 (-16.5357, 44.9076) -> (-21.0357, 44.9076)
sketch "Sketch59" plane through (0, 57.3945, 0) normal (0, 1, 0) x axis (-1, 0, 0)
extrude "Extrude41" add sketch "Sketch58" profile of L29 L30 L31 L32 L33 L34 L35 L36 L37 L38 L39 L40 L41 L42 L43 L44 L45 L46 L47 L48 L49 L50 L51 L52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 along normal blind 200
extrude "Extrude42" cut of existing geometry blind -400
extrude "Extrude43" cut of existing geometry blind -500
extrude "Extrude44" cut of existing geometry blind -500
extrude "Extrude45" cut of existing geometry blind -500
extrude "Extrude46" cut of existing geometry blind -500
sketch "Sketch60" plane through (0, 57.3945, 0) normal (0, 1, 0) x axis (-1, 0, 0)
  line L1 (-33.9524, -14.3624) -> (-33.9524, -5.9924)
  line L2 (41.0476, -14.3624) -> (-33.9524, -14.3624)
  line L3 (41.0476, -5.9924) -> (41.0476, -14.3624)
  line L4 (41.0199, -5.9924) -> (41.0476, -5.9924)
  line L5 (41.0199, 3.0076) -> (41.0199, -5.9924)
  line L6 (41.0476, 3.0076) -> (41.0199, 3.0076)
  line L7 (41.0476, 16.8876) -> (41.0476, 3.0076)
  line L8 (41.0199, 16.8876) -> (41.0476, 16.8876)
  line L9 (41.0199, 25.8876) -> (41.0199, 16.8876)
  line L10 (41.0476, 25.8876) -> (41.0199, 25.8876)
  line L11 (41.0476, 37.9076) -> (41.0476, 25.8876)
  line L12 (41.0199, 37.9076) -> (41.0476, 37.9076)
  line L13 (41.0199, 44.9076) -> (41.0199, 37.9076)
  line L14 (41.0476, 44.9076) -> (41.0199, 44.9076)
  line L15 (41.0476, 55.1376) -> (41.0476, 44.9076)
  line L16 (-33.9524, 55.1376) -> (41.0476, 55.1376)
  line L17 (-33.9524, 44.9076) -> (-33.9524, 55.1376)
  line L18 (-33.9246, 44.9076) -> (-33.9524, 44.9076)
  line L19 (-33.9246, 37.9076) -> (-33.9246, 44.9076)
  line L20 (-33.9524, 37.9076) -> (-33.9246, 37.9076)
  line L21 (-33.9524, 25.8876) -> (-33.9524, 37.9076)
  line L22 (-33.9246, 25.8876) -> (-33.9524, 25.8876)
  line L23 (-33.9246, 16.8876) -> (-33.9246, 25.8876)
  line L24 (-33.9524, 16.8876) -> (-33.9246, 16.8876)
  line L25 (-33.9524, 3.0076) -> (-33.9524, 16.8876)
  line L26 (-33.9246, 3.0076) -> (-33.9524, 3.0076)
  line L27 (-33.9246, -5.9924) -> (-33.9246, 3.0076)
  line L28 (-33.9524, -5.9924) -> (-33.9246, -5.9924)
  line L29 (28.131, -5.9924) -> (28.131, 3.0076)
  line L30 (23.631, -5.9924) -> (28.131, -5.9924)
  line L31 (23.631, 3.0076) -> (23.631, -5.9924)
  line L32 (28.131, 3.0076) -> (23.631, 3.0076)
  line L33 (13.2421, -5.9924) -> (13.2421, 3.0076)
  line L34 (8.7421, -5.9924) -> (13.2421, -5.9924)
  line L35 (8.7421, 3.0076) -> (8.7421, -5.9924)
  line L36 (13.2421, 3.0076) -> (8.7421, 3.0076)
  line L37 (28.131, 16.8876) -> (28.131, 25.8876)
  line L38 (23.631, 16.8876) -> (28.131, 16.8876)
  line L39 (23.631, 25.8876) -> (23.631, 16.8876)
  line L40 (28.131, 25.8876) -> (23.631, 25.8876)
  line L41 (28.131, 37.9076) -> (28.131, 44.9076)
  line L42 (23.631, 37.9076) -> (28.131, 37.9076)
  line L43 (23.631, 44.9076) -> (23.631, 37.9076)
  line L44 (28.131, 44.9076) -> (23.631, 44.9076)
  line L45 (13.2421, 16.8876) -> (13.2421, 25.8876)
  line L46 (8.7421, 16.8876) -> (13.2421, 16.8876)
  line L47 (8.7421, 25.8876) -> (8.7421, 16.8876)
  line L48 (13.2421, 25.8876) -> (8.7421, 25.8876)
  line L49 (13.2421, 37.9076) -> (13.2421, 44.9076)
  line L50 (8.7421, 37.9076) -> (13.2421, 37.9076)
  line L51 (8.7421, 44.9076) -> (8.7421, 37.9076)
  line L52 (13.2421, 44.9076) -> (8.7421, 44.9076)
  line L53 (-1.6468, -5.9924) -> (-1.6468, 3.0076)
  line L54 (-6.1468, -5.9924) -> (-1.6468, -5.9924)
  line L55 (-6.1468, 3.0076) -> (-6.1468, -5.9924)
  line L56 (-1.6468, 3.0076) -> (-6.1468, 3.0076)
  line L57 (-16.5357, -5.9924) -> (-16.5357, 3.0076)
  line L58 (-21.0357, -5.9924) -> (-16.5357, -5.9924)
  line L59 (-21.0357, 3.0076) -> (-21.0357, -5.9924)
  line L60 (-16.5357, 3.0076) -> (-21.0357, 3.0076)
  line L61 (-1.6468, 16.8876) -> (-1.6468, 25.8876)
  line L62 (-6.1468, 16.8876) -> (-1.6468, 16.8876)
  line L63 (-6.1468, 25.8876) -> (-6.1468, 16.8876)
  line L64 (-1.6468, 25.8876) -> (-6.1468, 25.8876)
  line L65 (-1.6468, 37.9076) -> (-1.6468, 44.9076)
  line L66 (-6.1468, 37.9076) -> (-1.6468, 37.9076)
  line L67 (-6.1468, 44.9076) -> (-6.1468, 37.9076)
  line L68 (-1.6468, 44.9076) -> (-6.1468, 44.9076)
  line L69 (-16.5357, 16.8876) -> (-16.5357, 25.8876)
  line L70 (-21.0357, 16.8876) -> (-16.5357, 16.8876)
  line L71 (-21.0357, 25.8876) -> (-21.0357, 16.8876)
  line L72 (-16.5357, 25.8876) -> (-21.0357, 25.8876)
  line L73 (-16.5357, 37.9076) -> (-16.5357, 44.9076)
  line L74 (-21.0357, 37.9076) -> (-16.5357, 37.9076)
  line L75 (-21.0357, 44.9076) -> (-21.0357, 37.9076)
  line L76 (-16.5357, 44.9076) -> (-21.0357, 44.9076)
sphere_primitive "SpherePrimitive1" Diameter 4
move "Move21"
move "Move22"
move_face "MoveFace12"
sketch "Sketch62" plane through (0, 25.8025, 63.1041) normal (0, 0.3785, 0.9256) x axis (-1, 0, 0)
  line L1 (41.0476, -15.7646) -> (41.0476, 45.0059)
  line L2 (168.5476, -15.7646) -> (41.0476, -15.7646)
  line L3 (168.5476, 45.0059) -> (168.5476, -15.7646)
  line L4 (41.0476, 45.0059) -> (168.5476, 45.0059)
  line L5 (168.5476, -15.7646) -> (125.1709, 45.0059)
  line L6 (125.1709, 45.0059) -> (168.5476, 45.0059)
  point P6 (125.1709, 45.0059)
  point P4 (168.5476, -15.7646)
  point P7 (168.5476, -15.7646)
  point P5 (168.5476, 45.0059)
  point P8 (168.5476, 45.0059)
  coincident L4 P6
  coincident P4 P7
  coincident P5 P8
sketch "Sketch63" plane through (0, -30.3449, 74.213) normal (0, -0.3785, 0.9256) x axis (1, 0, 0)
  line L1 (-41.0476, 15.6538) -> (-41.0476, -45.1167)
  line L2 (-168.5476, 15.6538) -> (-41.0476, 15.6538)
  line L3 (-168.5476, -45.1167) -> (-168.5476, 15.6538)
  line L4 (-41.0476, -45.1167) -> (-168.5476, -45.1167)
  line L5 (-168.5476, -45.1167) -> (-124.8523, 15.6538)
  line L6 (-168.5476, -45.1167) -> (-168.5476, 15.6538)
  line L7 (-124.8523, 15.6538) -> (-168.5476, 15.6538)
  point P6 (-124.8523, 15.6538)
  point P5 (-168.5476, -45.1167)
  point P7 (-168.5476, -45.1167)
  point P4 (-168.5476, 15.6538)
  point P8 (-168.5476, 15.6538)
  coincident L2 P6
  coincident P5 P7
  coincident P4 P8
split "Split6"
sketch "Sketch64" plane through (-168.5476, 0, 0) normal (-1, 0, 0) x axis (0, -1, 0)
  line L1 (-39.3945, 57.1376) -> (-40.3945, 57.1376)
  line L2 (-39.3945, 55.1376) -> (-39.3945, 57.1376)
  line L3 (71.1055, 55.1376) -> (-39.3945, 55.1376)
  line L4 (71.1055, 57.1376) -> (71.1055, 55.1376)
  line L5 (72.1055, 57.1376) -> (71.1055, 57.1376)
  line L6 (15.8555, 80.1376) -> (72.1055, 57.1376)
  line L7 (-40.3945, 57.1376) -> (15.8555, 80.1376)
  line L8 (72.1055, 57.1376) -> (-40.3945, 57.1376)
  point P2 (-40.3945, 57.1376)
  point P9 (-40.3945, 57.1376)
  point P7 (72.1055, 57.1376)
  point P10 (72.1055, 57.1376)
  coincident P2 P9
  coincident P7 P10
split "Split7"
sketch "Sketch65" plane through (0, -30.3449, 74.213) normal (0, -0.3785, 0.9256) x axis (1, 0, 0)
  line L1 (33.9524, -45.1167) -> (33.9524, 15.6538)
  line L2 (163.4524, -45.1167) -> (33.9524, -45.1167)
  line L3 (163.4524, 15.6538) -> (163.4524, -45.1167)
  line L4 (33.9524, 15.6538) -> (163.4524, 15.6538)
  line L5 (163.4524, -45.1167) -> (163.4524, 15.6538)
  point P5 (163.4524, 15.6538)
  point P6 (163.4524, 15.6538)
  point P4 (163.4524, -45.1167)
  point P7 (163.4524, -45.1167)
  coincident P5 P6
  coincident P4 P7
sketch "Sketch66" plane through (0, -30.3449, 74.213) normal (0, -0.3785, 0.9256) x axis (1, 0, 0)
move "Move2"
delete_face "DeleteFace7"
delete_face "DeleteFace8"
work_plane "WorkPlane2"
split "Split8"
move "Move3"
delete_face "DeleteFace9"
sketch "Sketch67" plane through (-60.6361, 0, 114.3564) normal (-0.4685, 0, 0.8835) x axis (0, -1, 0)
sketch "Sketch68" plane through (163.4524, 0, 0) normal (1, 0, 0) x axis (0, 1, 0)
  line L1 (-71.1055, 57.1376) -> (-72.1055, 57.1376)
  line L2 (-71.1055, 55.1376) -> (-71.1055, 57.1376)
  line L3 (39.3945, 55.1376) -> (-71.1055, 55.1376)
  line L4 (39.3945, 57.1376) -> (39.3945, 55.1376)
  line L5 (40.3945, 57.1376) -> (39.3945, 57.1376)
  line L6 (-15.8555, 80.1376) -> (40.3945, 57.1376)
  line L7 (-72.1055, 57.1376) -> (-15.8555, 80.1376)
sketch "Sketch69" plane through (0, -30.3449, 74.213) normal (0, -0.3785, 0.9256) x axis (1, 0, 0)
  line L1 (120, 15.6318) -> (163.4622, 15.6318)
  line L2 (163.4622, -45.1163) -> (120, 15.6318)
  horizontal L1
sketch "Sketch70" plane through (0, 25.8025, 63.1041) normal (0, 0.3785, 0.9256) x axis (-1, 0, 0)
  line L1 (-33.9524, 45.0059) -> (-33.9524, -15.7646)
  line L2 (-163.4524, 45.0059) -> (-33.9524, 45.0059)
  line L3 (-163.4524, -15.7646) -> (-163.4524, 45.0059)
  line L4 (-33.9524, -15.7646) -> (-163.4524, -15.7646)
  line L5 (-120.2362, 45.0059) -> (-163.4524, -15.7646)
  point P5 (-163.4524, -15.7646)
  point P6 (-163.4524, -15.7646)
  point P7 (-120.2362, 45.0059)
  coincident P5 P6
  coincident L2 P7
split "Split9"
split "Split10"
move "Move4"
delete_face "DeleteFace10"
delete_face "DeleteFace11"
sketch "Sketch71" plane through (0, 57.3945, 0) normal (0, 1, 0) x axis (-1, 0, 0)
extrude "Extrude51" cut sketch "Sketch60" profile of L57 L58 L59 L60 against normal blind 150
sketch "Sketch72" plane through (0, 57.3945, 0) normal (0, 1, 0) x axis (-1, 0, 0)
  line L1 (-33.9524, -14.3624) -> (-33.9524, -5.9924)
  line L2 (41.0476, -14.3624) -> (-33.9524, -14.3624)
  line L3 (41.0476, -5.9924) -> (41.0476, -14.3624)
  line L4 (41.0199, -5.9924) -> (41.0476, -5.9924)
  line L5 (41.0199, 3.0076) -> (41.0199, -5.9924)
  line L6 (41.0476, 3.0076) -> (41.0199, 3.0076)
  line L7 (41.0476, 16.8876) -> (41.0476, 3.0076)
  line L8 (41.0199, 16.8876) -> (41.0476, 16.8876)
  line L9 (41.0199, 25.8876) -> (41.0199, 16.8876)
  line L10 (41.0476, 25.8876) -> (41.0199, 25.8876)
  line L11 (41.0476, 37.9076) -> (41.0476, 25.8876)
  line L12 (41.0199, 37.9076) -> (41.0476, 37.9076)
  line L13 (41.0199, 44.9076) -> (41.0199, 37.9076)
  line L14 (41.0476, 44.9076) -> (41.0199, 44.9076)
  line L15 (41.0476, 55.1376) -> (41.0476, 44.9076)
  line L16 (-33.9524, 55.1376) -> (41.0476, 55.1376)
  line L17 (-33.9524, 44.9076) -> (-33.9524, 55.1376)
  line L18 (-33.9246, 44.9076) -> (-33.9524, 44.9076)
  line L19 (-33.9246, 37.9076) -> (-33.9246, 44.9076)
  line L20 (-33.9524, 37.9076) -> (-33.9246, 37.9076)
  line L21 (-33.9524, 25.8876) -> (-33.9524, 37.9076)
  line L22 (-33.9246, 25.8876) -> (-33.9524, 25.8876)
  line L23 (-33.9246, 16.8876) -> (-33.9246, 25.8876)
  line L24 (-33.9524, 16.8876) -> (-33.9246, 16.8876)
  line L25 (-33.9524, 3.0076) -> (-33.9524, 16.8876)
  line L26 (-33.9246, 3.0076) -> (-33.9524, 3.0076)
  line L27 (-33.9246, -5.9924) -> (-33.9246, 3.0076)
  line L28 (-33.9524, -5.9924) -> (-33.9246, -5.9924)
  line L29 (28.131, -5.9924) -> (28.131, 3.0076)
  line L30 (23.631, -5.9924) -> (28.131, -5.9924)
  line L31 (23.631, 3.0076) -> (23.631, -5.9924)
  line L32 (28.131, 3.0076) -> (23.631, 3.0076)
  line L33 (13.2421, -5.9924) -> (13.2421, 3.0076)
  line L34 (8.7421, -5.9924) -> (13.2421, -5.9924)
  line L35 (8.7421, 3.0076) -> (8.7421, -5.9924)
  line L36 (13.2421, 3.0076) -> (8.7421, 3.0076)
  line L37 (28.131, 16.8876) -> (28.131, 25.8876)
  line L38 (23.631, 16.8876) -> (28.131, 16.8876)
  line L39 (23.631, 25.8876) -> (23.631, 16.8876)
  line L40 (28.131, 25.8876) -> (23.631, 25.8876)
  line L41 (28.131, 37.9076) -> (28.131, 44.9076)
  line L42 (23.631, 37.9076) -> (28.131, 37.9076)
  line L43 (23.631, 44.9076) -> (23.631, 37.9076)
  line L44 (28.131, 44.9076) -> (23.631, 44.9076)
  line L45 (13.2421, 16.8876) -> (13.2421, 25.8876)
  line L46 (8.7421, 16.8876) -> (13.2421, 16.8876)
  line L47 (8.7421, 25.8876) -> (8.7421, 16.8876)
  line L48 (13.2421, 25.8876) -> (8.7421, 25.8876)
  line L49 (13.2421, 37.9076) -> (13.2421, 44.9076)
  line L50 (8.7421, 37.9076) -> (13.2421, 37.9076)
  line L51 (8.7421, 44.9076) -> (8.7421, 37.9076)
  line L52 (13.2421, 44.9076) -> (8.7421, 44.9076)
  line L53 (-1.6468, -5.9924) -> (-1.6468, 3.0076)
  line L54 (-6.1468, -5.9924) -> (-1.6468, -5.9924)
  line L55 (-6.1468, 3.0076) -> (-6.1468, -5.9924)
  line L56 (-1.6468, 3.0076) -> (-6.1468, 3.0076)
  line L57 (-16.5357, -5.9924) -> (-16.5357, 3.0076)
  line L58 (-21.0357, -5.9924) -> (-16.5357, -5.9924)
  line L59 (-21.0357, 3.0076) -> (-21.0357, -5.9924)
  line L60 (-16.5357, 3.0076) -> (-21.0357, 3.0076)
  line L61 (-1.6468, 16.8876) -> (-1.6468, 25.8876)
  line L62 (-6.1468, 16.8876) -> (-1.6468, 16.8876)
  line L63 (-6.1468, 25.8876) -> (-6.1468, 16.8876)
  line L64 (-1.6468, 25.8876) -> (-6.1468, 25.8876)
  line L65 (-1.6468, 37.9076) -> (-1.6468, 44.9076)
  line L66 (-6.1468, 37.9076) -> (-1.6468, 37.9076)
  line L67 (-6.1468, 44.9076) -> (-6.1468, 37.9076)
  line L68 (-1.6468, 44.9076) -> (-6.1468, 44.9076)
  line L69 (-16.5357, 16.8876) -> (-16.5357, 25.8876)
  line L70 (-21.0357, 16.8876) -> (-16.5357, 16.8876)
  line L71 (-21.0357, 25.8876) -> (-21.0357, 16.8876)
  line L72 (-16.5357, 25.8876) -> (-21.0357, 25.8876)
  line L73 (-16.5357, 37.9076) -> (-16.5357, 44.9076)
  line L74 (-21.0357, 37.9076) -> (-16.5357, 37.9076)
  line L75 (-21.0357, 44.9076) -> (-21.0357, 37.9076)
  line L76 (-16.5357, 44.9076) -> (-21.0357, 44.9076)
  line L77 (1, 0) -> (6, 0)
  line L78 (1, -10) -> (1, 0)
  line L79 (6, -10) -> (1, -10)
  line L80 (6, 0) -> (6, -10)
  horizontal L77
  vertical L78
  horizontal L79
  vertical L80
sphere_primitive "SpherePrimitive2" Diameter 3
move_face "MoveFace13"
move "Move23"
move "Move24"
move_face "MoveFace14"
move "Move25"
move "Move26"
move_face "MoveFace15"
sketch "Sketch74" plane through (0, 0, 0) normal (1, 0, 0) x axis (0, 1, 0)
sphere_primitive "SpherePrimitive3" Diameter 0.5
move_face "MoveFace16"
sphere_primitive "SpherePrimitive4" Diameter 1
mirror "Mirror7" mirrorStitchTolerance 0.1
move "Move27"
mirror "Mirror8" mirrorStitchTolerance 0.1
move "Move28"
mirror "Mirror9" mirrorStitchTolerance 0.1
move "Move29"
move "Move30"
move "Move31"
move "Move32"
move "Move33"
extrude "Extrude47" add of existing geometry blind 6
sketch "Sketch77" plane through (0, 0, 0) normal (0, 0, 1) x axis (1, 0, 0)
step "TorusPrimitive" MinorDiameter 0.5 MajorDiameter 1.97
extrude "Extrude52" add of existing geometry blind 9
extrude "Extrude53" add of existing geometry blind 4
sketch "Sketch79" plane through (0, 0, 55.6376) normal (0, 0, -1) x axis (1, 0, 0)
  line L1 (32, -39.3945) -> (-38.959, -39.3945)
  line L2 (32, -17.0793) -> (32, -39.3945)
  line L3 (33.9524, -17.0793) -> (32, -17.0793)
  line L4 (33.9524, -17.1616) -> (33.9524, -17.0793)
  line L5 (157.9638, -17.1616) -> (33.9524, -17.1616)
  line L6 (157.9638, 61.1302) -> (157.9638, -17.1616)
  line L7 (33.9524, 61.1302) -> (157.9638, 61.1302)
  line L8 (33.9524, 61) -> (33.9524, 61.1302)
  line L9 (32, 61) -> (33.9524, 61)
  line L10 (32, 78) -> (32, 61)
  line L11 (-39, 78) -> (32, 78)
  line L12 (-39, 61) -> (-39, 78)
  line L13 (-41.0476, 61) -> (-39, 61)
  line L14 (-41.0476, -17.0793) -> (-41.0476, 61)
  line L15 (-39.0985, -17.0793) -> (-41.0476, -17.0793)
  line L16 (-39.0985, -19) -> (-39.0985, -17.0793)
  line L17 (-38.959, -19) -> (-39.0985, -19)
  line L18 (-38.959, -39.3945) -> (-38.959, -19)
  line L19 (147.4418, -30) -> (22, -30)
  line L20 (147.4418, -16.8082) -> (147.4418, -30)
  line L21 (22, -16.8082) -> (147.4418, -16.8082)
  line L22 (22, -30) -> (22, -16.8082)
  horizontal L19
  vertical L20
  horizontal L21
  vertical L22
